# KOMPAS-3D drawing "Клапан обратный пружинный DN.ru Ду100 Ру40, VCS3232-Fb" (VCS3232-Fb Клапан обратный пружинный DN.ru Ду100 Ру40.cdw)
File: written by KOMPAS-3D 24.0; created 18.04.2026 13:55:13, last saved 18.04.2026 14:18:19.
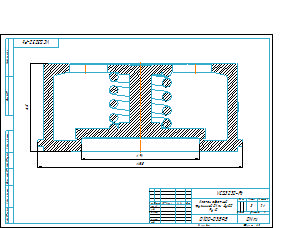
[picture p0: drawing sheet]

Document properties: c3d_UniqueCompID: 071bd168-1a06-425c-849c-e99e84a96128; Наименование: Деталь; Автор: 712; Класс точности: c; Знак неуказанной шероховатости: Шероховатость не задана; Рассекать на разрезах: Да; c3d_UniqueCompID: 071bd168-1a06-425c-849c-e99e84a96128; Наименование: Деталь; Автор: 712; Класс точности: c; Знак неуказанной шероховатости: Шероховатость не задана; Рассекать на разрезах: Да; c3d_UniqueCompID: 071bd168-1a06-425c-849c-e99e84a96128; Наименование: Деталь; Автор: 712; Класс точности: c; Знак неуказанной шероховатости: Шероховатость не задана; Рассекать на разрезах: Да; c3d_UniqueCompID: 071bd168-1a06-425c-849c-e99e84a96128; Наименование: Деталь; Автор: 712; Класс точности: c; Знак неуказанной шероховатости: Шероховатость не задана; Рассекать на разрезах: Да; c3d_UniqueCompID: 071bd168-1a06-425c-849c-e99e84a96128; Наименование: Деталь; Автор: 712; Класс точности: c; Знак неуказанной шероховатости: Шероховатость не задана; Рассекать на разрезах: Да; c3d_UniqueCompID: 071bd168-1a06-425c-849c-e99e84a96128; Наименование: Деталь; Автор: 712; Класс точности: c; Знак неуказанной шероховатости: Шероховатость не задана; Рассекать на разрезах: Да; c3d_UniqueCompID: 071bd168-1a06-425c-849c-e99e84a96128; Наименование: Деталь; Автор: 712; Класс точности: c; Знак неуказанной шероховатости: Шероховатость не задана; Рассекать на разрезах: Да; c3d_UniqueCompID: 071bd168-1a06-425c-849c-e99e84a96128; Наименование: Деталь; Автор: 712; Класс точности: c; Знак неуказанной шероховатости: Шероховатость не задана; Рассекать на разрезах: Да; c3d_UniqueCompID: 071bd168-1a06-425c-849c-e99e84a96128; Наименование: Деталь; Автор: 712; Класс точности: c; Знак неуказанной шероховатости: Шероховатость не задана; Рассекать на разрезах: Да; Автор: 712; Форматы листов документа: A3; Полное имя файла: VCS3232-Fb Клапан обратный пружинный DN.ru Ду100 Ру40.m3d; Масса: 3; Наименование: Клапан обратный пружинный DN.ru Ду100 Ру40; Количество листов документа: 1; Примечание: D100-03898

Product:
- Component: Пружина 1086-1017 ГОСТ 18793-80  | qty 1  | additional columns: 3953604318-4147491677-0; Деталь; Пользователь Windows; c; Шероховатость не задана; Да; Сталь 10  ГОСТ 1050-88; source file: Деталь.m3d
- Body: Тело 1  | qty 1
    Масса: 3.671618
- Part/product: Клапан обратный пружинный DN.ru Ду100 Ру40  | designation VCS3232-Fb
    Масса: 3
    Раздел спецификации: Прочие изделия
    Примечание: D100-03898
    additional columns: 071bd168-1a06-425c-849c-e99e84a96128; Деталь; 712; c; Шероховатость не задана; Да

Views: Вид 1, Местный разрез 1, Спереди
Referenced files in C:\Users\712\Desktop\Новая папка (4)\: VCS3232-Fb Клапан обратный пружинный DN.ru Ду15 Ру40.m3d, VCS3232-Fb Клапан обратный пружинный DN.ru Ду100 Ру40.m3d, VCS3232-Fb Клапан обратный пружинный DN.ru Ду15 Ру40.cdw
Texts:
  VCS3232-Fb
  Клапан обратный
  пружинный DN.ru Ду100
  Ру40
  Клапан обратный пружинный DN.ru Ду100 Ру40
  VCS3232-Fb Клапан обратный пружинный DN.ru Ду100 Ру40
Dimensions and other numbers on the sheet: 0; 3; 2; 4; 158; 91; 68; 2:1; 1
